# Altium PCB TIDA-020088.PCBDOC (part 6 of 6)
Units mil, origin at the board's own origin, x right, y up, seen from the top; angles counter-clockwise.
Board outline 7520.69 x 5119.11 mil, 6 copper layers (TOP, GND02, SIG03, SIG04, GND05, BOTTOM), stack 87.024 mil thick; 539 components, 269 nets, 1479 pads, 2085 vias.
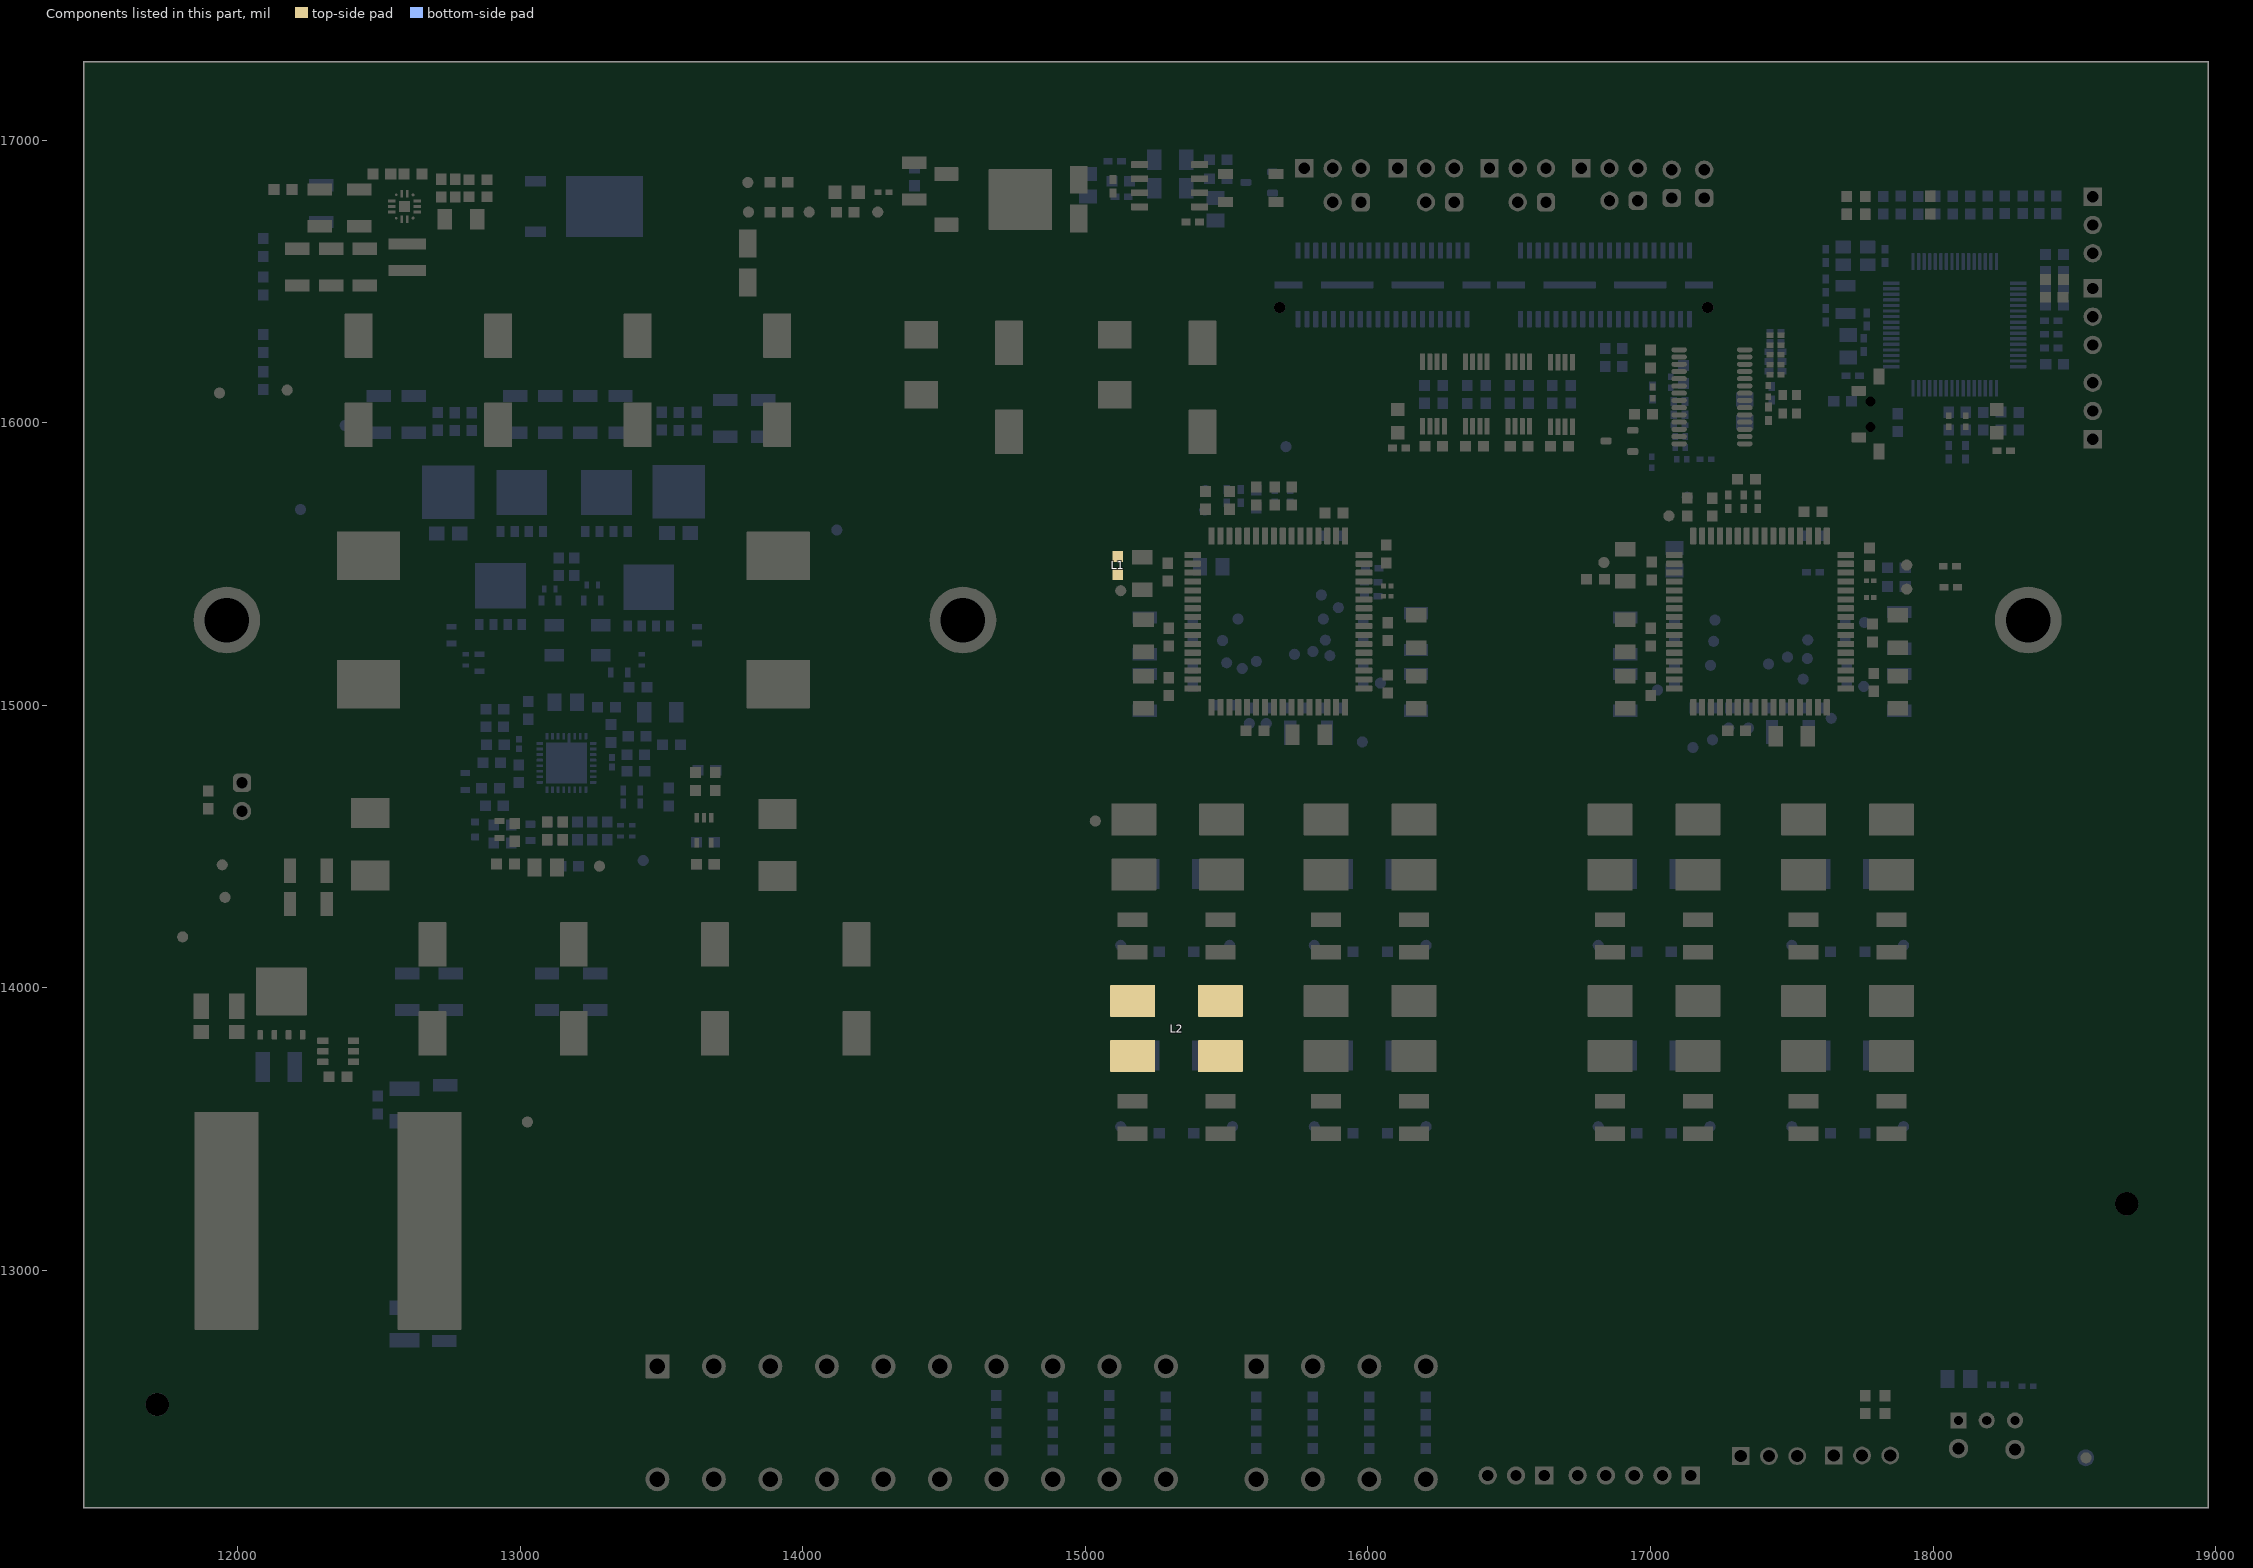
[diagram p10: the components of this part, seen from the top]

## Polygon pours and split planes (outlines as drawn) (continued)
PVDD_2 on TOP "PVDD_2_L01_P1359" (solid, pour order 1359): 19 vertices, not listed, extent 16790,14870 17165,15070
GND on TOP "GND_L01_P1358" (solid, pour order 1358): 17061.82,15230.84 17111.61,15230.84 17119.89,15222.56 17119.89,15152.56 17111.55,15144.22 17111.55,15143.22 17045.55,15143.22 17034.89,15132.56 17034.89,15088.87 17013.58,15067.56 16779.89,15067.56 16774.89,15072.56 16774.89,15217.56 16788.17,15230.84
PVDD_2 on TOP "PVDD_2_L01_P1357" (solid, pour order 1357): 17010,15360 17035,15385 17115,15385 17120,15380 17120,15310 17110,15300 17045,15300 17035,15290 17035,15246.47 17028.53,15240 16800,15240 16775,15265 16775,15340 16795,15360
NETC13_1 on TOP "NETC13_1_L01_P1356" (solid, pour order 1356): 15300,15475 15105,15475 15092.5,15462.5 15092.5,15407.5 15110,15390 15300,15390 15312.2,15402.2 15312.2,15462.8
NETC65_1 on TOP "NETC65_1_L01_P1355" (solid, pour order 1355): 17020,15470 16825,15470 16812.5,15457.5 16812.5,15402.5 16830,15385 17020,15385 17032.2,15397.2 17032.2,15457.8
BIAS on TOP "BIAS_L01_P1349" (solid, pour order 1349): 16785,15540 16665,15540 16652.5,15527.5 16652.5,15432.5 16670,15415 16780,15415 16795,15430 16795,15530
NETC37_2 on TOP "NETC37_2_L01_P1299" (solid, pour order 1299): 20 vertices, not listed, extent 15875,14520 16255,15025
GND on TOP "GND_L01_P1293" (solid, pour order 1293): 15780,15022.2 15781.34,15023.54 15831.46,15023.54 15835,15020 15835,14965 15835,14955 15855,14935 15865,14935 15885,14915 15885,14735 15875,14725 15790,14725 15780,14735
PVDD_1 on TOP "PVDD_1_L01_P1292" (solid, pour order 1292): 15660,15025 15705,15025 15710.55,15019.45 15710.55,14959.45 15720,14950 15765,14950 15775,14940 15775,14775 15755,14755 15630,14755 15610,14775 15610,14935 15625,14950 15655,14950 15655,15020
NETC29_2 on TOP "NETC29_2_L01_P1344" (solid, pour order 1344): 15391.07,14675.47 15629.53,14675.47 15645.49,14659.51 15645.49,14540.49 15630.47,14525.47 15394.91,14525.47 15372.47,14547.91 15372.47,14656.88
NETC38_1 on TOP "NETC38_1_L01_P1343" (solid, pour order 1343): 15686.07,14670.47 15924.53,14670.47 15940.49,14654.51 15940.49,14535.49 15925.47,14520.47 15689.91,14520.47 15667.47,14542.91 15667.47,14651.88
NETC90_1 on TOP "NETC90_1_L01_P1338" (solid, pour order 1338): 17375.47,14675.47 17614.53,14675.47 17635,14655 17635,14545 17615.47,14525.47 17369.9,14525.47 17360,14535.38 17360,14660
NETC97_2 on TOP "NETC97_2_L01_P1337" (solid, pour order 1337): 17766.07,14030.47 18004.53,14030.47 18020.49,14014.51 18020.49,13895.49 18005.47,13880.47 17769.9,13880.47 17747.47,13902.91 17747.47,14011.88
NETC74_1 on TOP "NETC74_1_L01_P1328" (solid, pour order 1328): 16686.07,14030.47 16924.53,14030.47 16940.49,14014.51 16940.49,13895.49 16925.47,13880.47 16689.9,13880.47 16667.47,13902.91 16667.47,14011.88
NETC45_2 on TOP "NETC45_2_L01_P1323" (solid, pour order 1323): 16086.07,14030.47 16324.53,14030.47 16340.49,14014.51 16340.49,13895.49 16325.47,13880.47 16089.91,13880.47 16067.47,13902.91 16067.47,14011.88
NETC19_2 on TOP "NETC19_2_L01_P1321" (solid, pour order 1321): 15393.08,14023.08 15671.92,14023.08 15689.48,14005.52 15689.48,13894.48 15668.08,13873.08 15396.92,13873.08 15374.48,13895.52 15374.48,14004.48
NETC22_1 on TOP "NETC22_1_L01_P1310" (solid, pour order 1310): 14971.16,14025 15250,14025 15267.56,14007.44 15267.56,13896.4 15246.16,13875 14975,13875 14952.56,13897.44 14952.56,14006.4
BIAS on TOP "BIAS_L01_P1309" (solid, pour order 1309): 14825,15565 15125,15565 15143.54,15546.46 15143.54,15513.54 15125,15495 15015,15495 14965,15445 14830,15445 14810,15465 14810,15550
PVDD_1 on TOP "PVDD_1_L01_P1305" (solid, pour order 1305): 18 vertices, not listed, extent 15954.22,15270 16225,15360
GND on TOP "GND_L01_P1303" (solid, pour order 1303): 19 vertices, not listed, extent 15950,15077.32 16225,15250.87
NETC45_2 on TOP "NETC45_2_L01_P1302" (solid, pour order 1302): 16017.95,15274.73 16012.95,15269.73 15947.95,15269.73 15927.95,15249.73 15872.95,15249.73 15862.95,15259.73 15862.95,15314.73 15872.95,15324.73 15927.95,15324.73 15937.95,15314.73 15937.95,15294.73 15942.95,15289.73 16012.95,15289.73 16017.95,15284.73
NETC46_1 on TOP "NETC46_1_L01_P1301" (solid, pour order 1301): 16018.18,15085.8 16013.18,15080.8 15948.18,15080.8 15928.18,15060.8 15873.18,15060.8 15863.18,15070.8 15863.18,15125.8 15873.18,15135.8 15928.18,15135.8 15938.18,15125.8 15938.18,15105.8 15943.18,15100.8 16013.18,15100.8 16018.18,15095.8
PVDD_1 on TOP "PVDD_1_L01_P1300" (solid, pour order 1300): 15956.26,15071.06 16107.04,15071.06 16120,15058.1 16120,15040 16135,15025 16210,15025 16225,15010 16225,14860 16200,14835 16105,14835 15980,14960 15911.28,14960 15905.81,14965.47 15905.81,15021.54 15955.33,15071.07
NETC38_1 on TOP "NETC38_1_L01_P1295" (solid, pour order 1295): 15765.02,15120.62 15775.02,15110.62 15775.02,15050.64 15742.2,15028.72 15742.2,14963.95 15740.28,14962.02 15720.39,14962.02 15717.86,14964.55 15717.86,15032.56 15698.77,15051.65 15698.77,15110.81 15708.59,15120.62
NETC29_2 on TOP "NETC29_2_L01_P1294" (solid, pour order 1294): 15670,15120 15680,15110 15680,15050.02 15647.19,15028.1 15647.19,14963.32 15645.26,14961.4 15625.37,14961.4 15622.84,14963.93 15622.84,15031.94 15603.76,15051.03 15603.76,15110.19 15613.57,15120
GND on TOP "GND_L01_P1291" (solid, pour order 1291): 15530,15027.2 15531.34,15028.54 15581.46,15028.54 15585,15025 15585,14955 15600,14940 15600,14820 15590,14810 15540,14810 15530,14820
PVDD_1 on TOP "PVDD_1_L01_P1288" (solid, pour order 1288): 19 vertices, not listed, extent 15085,14870 15460,15070
NETC19_2 on TOP "NETC19_2_L01_P1286" (solid, pour order 1286): 15345,15095 15350,15100 15415,15100 15435,15120 15490,15120 15500,15110 15500,15055 15490,15045 15435,15045 15425,15055 15425,15075 15420,15080 15350,15080 15345,15085
NETC22_1 on TOP "NETC22_1_L01_P1285" (solid, pour order 1285): 15350,15285 15355,15290 15415,15290 15425,15300 15425,15340 15435,15350 15495,15350 15505,15340 15505,15275 15495,15265 15355,15265 15350,15270
PVDD_1 on TOP "PVDD_1_L01_P1284" (solid, pour order 1284): 15110,15345 15290,15345 15330,15385 15410,15385 15415,15380 15415,15310 15405,15300 15340,15300 15330,15290 15330,15246.47 15323.53,15240 15100,15240 15090,15250 15090,15340 15095,15345
3.3V-SPDIF on TOP "3.3V-SPDIF_L01_P1276" (solid, pour order 1276): 16985,16045 16985,15975 16995,15965 17055,15965 17065,15975 17065,16047 17052,16060 17000,16060
VCC on TOP "VCC_L01_P1275" (solid, pour order 1275): 16830,16045 16830,16010 16840,16000 16960,16000 16970,16010 16970,16045 16960,16055 16840,16055
3V3 on TOP "3V3_L01_P1274" (solid, pour order 1274): 14280,16770 14170,16770 14157.5,16757.5 14157.5,16642.5 14170,16630 14275,16630 14290,16645 14290,16760
VCC on TOP "VCC_L01_P1273" (solid, pour order 1273): 14120,16900 13935,16900 13917.5,16882.5 13917.5,16647.5 13935,16630 14120,16630 14140,16650 14140,16880
VCC_BUCK on TOP "VCC_BUCK_L01_P1272" (solid, pour order 1272): 17 vertices, not listed, extent 12850,16455 13910,16900
VCC_LDO on TOP "VCC_LDO_L01_P1271" (solid, pour order 1271): 13150,16555 13185,16520 13665,16520 13715,16570 13865,16570 13910,16615 13910,16765 13890,16785 13695,16785 13665,16755 13665,16700 13620,16655 13185,16655 13150,16620
VCC_BUCK on TOP "VCC_BUCK_L01_P1266" (solid, pour order 1266): 12140,16510 12160,16530 12490,16530 12525,16565 12950,16565 12970,16545 12970,16475 12950,16455 12155,16455 12140,16470
NETL15_1 on TOP "NETL15_1_L01_P1265" (solid, pour order 1265): 17 vertices, not listed, extent 12525,16590 12675,16735
NetC120_1 on TOP "NETC120_1_L01_P1197" (solid, remove dead copper, pour order 1197): 12170,16840 12180,16850 12550,16850 12560,16840 12560,16765 12555,16760 12205,16760 12170,16795
BIAS on TOP "BIAS_L01_P1264" (solid, pour order 1264): 11815,16850 12145,16850 12155,16840 12155,16665 12120,16630 11810,16630 11785,16655 11785,16830 11805,16850
SW2 on TOP "SW2_L01_P1225" (solid, pour order 1225): 13725,15735 14220,15735 14235,15720 14235,15360 14210,15335 13645,15335 13290,15335 13260,15365 13260,15630 13270,15640 13675,15640 13700,15665 13700,15715
PVDD_2 on TOP "PVDD_2_L01_P1239" (solid, pour order 1239): 14995,16135 15030,16170 15165,16170 15220,16115 15565,16115 15635,16045 15635,15852.5 15607.5,15825 15017.5,15825 14995,15847.5
PVDD_1 on TOP "PVDD_1_L01_P1228" (solid, pour order 1228): 14332.5,16132.5 14367.5,16167.5 14502.5,16167.5 14557.5,16112.5 14902.5,16112.5 14972.5,16042.5 14972.5,15850 14945,15822.5 14355,15822.5 14332.5,15845
VOUT on TOP "VOUT_L01_P1227" (solid, pour order 1227): 14130,16175 14130,16500 14170,16540 14480,16540 14495,16525 14495,16390 14280,16175
VOUT on TOP "VOUT_L01_P1226" (solid, pour order 1226): 34 vertices, not listed, extent 11905,15650 15225,16540
L2 on TOP "L2_L01_P1221" (solid, pour order 1221): 14145,15280 13680,15280 13660,15260 13660,14900 13680,14880 14145,14880 14165,14900 14165,15260
L1 on TOP "L1_L01_P1219" (solid, pour order 1219): 12695,15280 12180,15280 12151.87,15251.87 12151.87,14593.13 12180,14565 12690,14565 12715,14590 12715,15260
BIAS on TOP "BIAS_L01_P1216" (solid, pour order 1216): 13385,14360 13770,14360 13800,14390 13800,14420 13829.14,14449.14 14001.72,14449.14 14365.86,14449.14 14395,14420 14395,14010 14370,13985 13385,13985
BAT_IN on TOP "BAT_IN_L01_P1201" (solid, pour order 1201): 13030,13575 13050,13555 13050,13450 13020,13420 12950,13420 12930,13400 12930,12810 12910,12790 12800,12790 12400,12790 12330,12860 12330,13520 12385,13575 12395,13575
BIAS on SIG03 "BIAS_L03_P1242" (solid, pour order 1242): 11870,14095 12430,14095 14375,14095 14395,14115 14395,14337.54 14372.54,14360 12630,14360 12560,14430 11880,14430 11710,14260 11710,14255
GND on SIG03 "GND_L03_P1534" (solid, remove dead copper, pour order 1534): 11450,17280 18967.57,17280 18967.57,12165.28 11450,12165.28
BIAS on SIG03 "BIAS_L03_P1354" (solid, pour order 1354): 15545.22,15540 16725,15540 16740.22,15524.78 16740.22,15475.22 16721.38,15456.38 14818.62,15456.38 14800,15475 14800,15515 14825,15540
AGND on SIG03 "AGND_L03_P1506" (solid, pour order 1506): 12725,14960 12725,14465 12785,14405 13470,14405 13565,14500 13565,15040 13555,15050 12815,15050
NETC74_1 on SIG03 "NETC74_1_L03_P1375" (solid, pour order 1375): 26 vertices, not listed, extent 16524.2,13890.22 17214.2,15360.22
NETC22_1 on SIG03 "NETC22_1_L03_P1319" (solid, pour order 1319): 27 vertices, not listed, extent 14815,13890 15505,15360
SPK_OUT4+ on SIG03 "SPK_OUT4+_L03_P1444" (solid, pour order 1444): 22 vertices, not listed, extent 15185,12185 16160,13480
SPK_OUT8+ on SIG03 "SPK_OUT8+_L03_P1464" (solid, pour order 1464): 17 vertices, not listed, extent 16110,12185 18040,13541
SPK_OUT7- on SIG03 "SPK_OUT7-_L03_P1463" (solid, pour order 1463): 21 vertices, not listed, extent 15962.63,12545 17572.97,14185.33
SPK_OUT6+ on SIG03 "SPK_OUT6+_L03_P1462" (solid, pour order 1462): 22 vertices, not listed, extent 15725,12210 17245,14130
SPK_OUT6- on SIG03 "SPK_OUT6-_L03_P1454" (solid, pour order 1454): 22 vertices, not listed, extent 15680,12560 16955,14190
SPK_OUT3- on SIG03 "SPK_OUT3-_L03_P1458" (solid, pour order 1458): 21 vertices, not listed, extent 15045,12545 15815,14180
SPK_OUT2+ on SIG03 "SPK_OUT2+_L03_P1455" (solid, pour order 1455): 15305,13990 15305,14070 15340,14105 15505,14105 15525,14085 15525,14040 15490,14005 15445,14005 15430,13990
SPK_OUT2+ on SIG03 "SPK_OUT2+_L03_P1436" (solid, pour order 1436): 15305,13990 15430,13990 15430,13160 15040,12770 15040,12320 14905,12185 14860,12185 14810,12235 14810,12320 14865,12375 14930,12440 14930,12890 15305,13265
SPK_OUT2- on SIG03 "SPK_OUT2-_L03_P1433" (solid, pour order 1433): 18 vertices, not listed, extent 14740,12570 15265,14185.22
SPK_OUT1- on SIG03 "SPK_OUT1-_L03_P1432" (solid, pour order 1432): 14964.89,13523.92 14964.97,13523.83 15086.17,13523.83 15105.48,13504.52 15105.48,13380.48 14735,13010 14735,12595 14710,12570 14570,12570 14540,12600 14540,13099.03
NETC97_2 on SIG03 "NETC97_2_L03_P1382" (solid, pour order 1382): 28 vertices, not listed, extent 17560,13885 18050.49,15324.73
NETC98_1 on SIG03 "NETC98_1_L03_P1380" (solid, pour order 1380): 17571.55,15140.31 17636.55,15140.31 17651.55,15125.31 17651.55,14060.31 17683.47,14028.39 17708.47,14028.39 17726.55,14010.31 17726.55,13900.31 17704.63,13878.39 17618.47,13878.39 17578.04,13918.82 17578.04,15017.37 17565.11,15030.31 17554.74,15040.68 17554.74,15123.49
NETC90_1 on SIG03 "NETC90_1_L03_P1379" (solid, pour order 1379): 18 vertices, not listed, extent 17362.47,14520 17540,15120.62
NETC81_2 on SIG03 "NETC81_2_L03_P1378" (solid, pour order 1378): 17299.73,15111.96 17309.54,15121.77 17373.98,15121.77 17383.34,15112.41 17383.34,14694.14 17340.97,14651.77 17340.97,14541.77 17326.45,14527.25 17261.45,14527.25 17260.97,14526.77 17245.97,14541.77 17245.97,14764.26 17299.73,14818.02
NETC71_2 on SIG03 "NETC71_2_L03_P1376" (solid, pour order 1376): 17130,15105 17150,15125 17205,15125 17225,15105 17225,14505 17375,14355 17375,13900 17365,13890 17270,13890 17250,13910 17250,14330 17130,14450
NETC45_2 on SIG03 "NETC45_2_L03_P1352" (solid, pour order 1352): 28 vertices, not listed, extent 15850,13880 16340.49,15319.73
NETC46_1 on SIG03 "NETC46_1_L03_P1350" (solid, pour order 1350): 15880,15135 15945,15135 15960,15120 15960,14055 15991.92,14023.08 16016.92,14023.08 16035,14005 16035,13895 16013.08,13873.08 15926.92,13873.08 15880,13920 15880,15018.56 15873.56,15025 15863.18,15035.37 15863.18,15118.19
NETC38_1 on SIG03 "NETC38_1_L03_P1348" (solid, pour order 1348): 18 vertices, not listed, extent 15667.47,14520 15845,15120.62
NETC29_2 on SIG03 "NETC29_2_L03_P1347" (solid, pour order 1347): 15595,15101.43 15613.57,15120 15678.01,15120 15687.37,15110.64 15687.37,14692.37 15645,14650 15645,14540 15630.47,14525.47 15565.47,14525.47 15565,14525 15550,14540 15550,14762.49 15595,14807.49
NETC19_2 on SIG03 "NETC19_2_L03_P1346" (solid, pour order 1346): 15415,15100 15435,15120 15490,15120 15510,15100 15510,14325 15545,14290 15640,14290 15660,14270 15660,13895 15650,13885 15555,13885 15535,13905 15535,14135 15415,14255
3.3V-SPDIF on SIG03 "3.3V-SPDIF_L03_P1278" (solid, pour order 1278): 17025,16335 17060,16370 17470,16370 17490,16350 17490,15965 17465,15940 17050,15940 17025,15965
BIAS on SIG03 "BIAS_L03_P1261" (solid, pour order 1261): 21 vertices, not listed, extent 11620,14171.36 12600,16805
VOUT on SIG03 "VOUT_L03_P1251" (solid, pour order 1251): 33 vertices, not listed, extent 12110,15650 15225,16540
PVDD_2 on SIG03 "PVDD_2_L03_P1255" (solid, pour order 1255): 14995,16135 15030,16170 15165,16170 15220,16115 15565,16115 15635,16045 15635,15852.5 15607.5,15825 15017.5,15825 14995,15847.5
PVDD_1 on SIG03 "PVDD_1_L03_P1256" (solid, pour order 1256): 14332.5,16132.5 14367.5,16167.5 14502.5,16167.5 14557.5,16112.5 14902.5,16112.5 14972.5,16042.5 14972.5,15850 14945,15822.5 14355,15822.5 14332.5,15845
VOUT on SIG03 "VOUT_L03_P1253" (solid, pour order 1253): 14130,16175 14130,16500 14170,16540 14480,16540 14495,16525 14495,16390 14280,16175
SW2 on SIG03 "SW2_L03_P1248" (solid, pour order 1248): 13725,15735 14220,15735 14235,15720 14235,15360 14210,15335 13645,15335 13290,15335 13260,15365 13260,15630 13270,15640 13675,15640 13700,15665 13700,15715
SW1 on SIG03 "SW1_L03_P1246" (solid, pour order 1246): 12190,15725 12600,15725 12625,15700 12625,15650 12635,15640 13091.54,15640 13100,15631.54 13100,15485 13100,15365 13085,15350 13070,15335 12210,15335 12175,15370 12175,15610 12175,15710
BAT_IN on SIG03 "BAT_IN_L03_P1199" (solid, pour order 1199): 14485,12475 12810,12475 12770,12515 12770,13540 12805,13575 14475,13575 14525,13525 14525,12515
BIAS on SIG04 "BIAS_L04_P1535" (solid, pour order 1535): 12035,16640 11955,16640 11940,16655 11940,16845 11989.32,16894.32 14204.32,16894.32 14265,16955 14345,16955 14365,16935 14365,16878.15 14296.85,16810 12105,16810 12050,16755 12050,16655
GND on SIG04 "GND_L04_P1538" (solid, remove dead copper, pour order 1538): 11448.8,17280.82 18966.37,17280.82 18966.37,12166.09 11448.8,12166.09
BIAS on SIG04 "BIAS_L04_P1532" (solid, pour order 1532): 14360,14360 14525,14360 14804.92,14639.92 14804.92,15544.92 14825,15565 14950,15565 14980,15535 14980,14475 14610,14105 14325,14105 14325,14325
3V3 on SIG04 "3V3_L04_P1505" (solid, pour order 1505): 26 vertices, not listed, extent 17440,16090 18640,16621.5
SPK_OUT8- on SIG04 "SPK_OUT8-_L04_P1461" (solid, pour order 1461): 17366.29,13510.32 17384.89,13528.92 17521.08,13528.92 17545,13505 17545,13295 16830,12580 16285,12580 16255,12550 16175,12550 16163.51,12561.49 16163.51,12708.51 16180,12725 16740,12725 17366.29,13351.29
SPK_OUT5+ on SIG04 "SPK_OUT5+_L04_P1448" (solid, pour order 1448): 27 vertices, not listed, extent 15480,12180 17350,13528.92
SPK_OUT1+ on SIG04 "SPK_OUT1+_L04_P1456" (solid, pour order 1456): 15500,13560 15645,13560 15657.3,13547.7 15657.3,13512.3 15600,13455 15495.09,13455 15475,13475.09 15475,13535
SPK_OUT4- on SIG04 "SPK_OUT4-_L04_P1439" (solid, pour order 1439): 18 vertices, not listed, extent 15205,12550 15805,13540
SPK_OUT3+ on SIG04 "SPK_OUT3+_L04_P1451" (solid, pour order 1451): 26 vertices, not listed, extent 15015,12180 16505,14195
SPK_OUT7+ on SIG04 "SPK_OUT7+_L04_P1446" (solid, pour order 1446): 23 vertices, not listed, extent 15940,12195 18045,14180
SPK_OUT5- on SIG04 "SPK_OUT5-_L04_P1443" (solid, pour order 1443): 19 vertices, not listed, extent 15535,12545 16840,13528.92
SPK_OUT1+ on SIG04 "SPK_OUT1+_L04_P1434" (solid, pour order 1434): 15477.5,13537.5 15545,13537.5 15545,13465 14840,12760 14840,12335 14685,12180 14630,12180 14575,12235 14575,12320 14590,12335 14630,12335 14730,12435 14730,12790
PVDD_1 on SIG04 "PVDD_1_L04_P1431" (solid, pour order 1431): 14375,15895 14685,15585 14945,15585 15090,15440 15090,15330 15695,15330 15705,15340 15690,15355 15645,15355 15315,15685 15205,15685 14935,15955 14395,15955 14375,15935
PVDD_2 on SIG04 "PVDD_2_L04_P1430" (solid, pour order 1430): 15035,16045 15015,16025 15015,15895 15215,15695 15330,15695 15625,15400 15860,15635 15860,15820 15635,16045
PVDD_2 on SIG04 "PVDD_2_L04_P1427" (solid, pour order 1427): 15330,15695 15625,15400 16205,15400 16270,15335 16270,14835 16330,14775 16940,14775 16940,15230 16940,15360 16480,15820 15860,15820 15635,16045 15330,16045
PVDD_2 on SIG04 "PVDD_2_L04_P1353" (solid, pour order 1353): 17857.67,14777.56 16817.67,14777.56 16777.67,14817.56 16777.67,15342.56 16797.67,15362.56 17877.67,15362.56 17912.67,15327.56 17912.67,14832.56
PVDD_1 on SIG04 "PVDD_1_L04_P1315" (solid, pour order 1315): 16120,14725 15180,14725 15090,14815 15090,15340 15110,15360 16190,15360 16225,15325 16225,14830
PVDD_1 on SIG04 "PVDD_1_L04_P1254" (solid, pour order 1254): 14392.5,16042.5 14952.5,16042.5 14972.5,16022.5 14972.5,15897.5 14950,15875 14395,15875 14375,15895 14375,16025
VOUT on SIG04 "VOUT_L04_P1250" (solid, pour order 1250): 20 vertices, not listed, extent 11905,15652.5 14180,16142.5
SW2 on SIG04 "SW2_L04_P1249" (solid, pour order 1249): 13725,15735 14220,15735 14235,15720 14235,15360 14210,15335 13645,15335 13290,15335 13260,15365 13260,15630 13270,15640 13675,15640 13700,15665 13700,15715
SW1 on SIG04 "SW1_L04_P1247" (solid, pour order 1247): 12190,15725 12600,15725 12625,15700 12625,15650 12635,15640 13091.54,15640 13100,15631.54 13100,15485 13100,15365 13085,15350 13070,15335 12210,15335 12175,15370 12175,15610 12175,15710
BIAS on SIG04 "BIAS_L04_P1243" (solid, pour order 1243): 12315,14105 14340,14105 14395,14160 14395,14330 14365,14360 14025,14360 13770,14360 12630,14360 12315,14360 12290,14335 12290,14130
BAT_IN on SIG04 "BAT_IN_L04_P1200" (solid, pour order 1200): 14515,12475 12810,12475 12770,12515 12770,13540 12805,13575 14505,13575 14560,13520 14560,12520
GND on GND02 "GND_L02_P1533" (solid, remove dead copper, pour order 1533): 11454.56,17277.48 18972.13,17277.48 18972.13,12162.76 11454.56,12162.76
no net on Bottom Solder "Bottom Solder-No Net" (solid): 132 vertices, not listed, extent 11474.56,12180 18954,17254.71

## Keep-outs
TOP:
  circle w1: c25911,29728 r42.87
  circle w1: c26096,29728 r42.87
  circle w1: c26281,29728 r42.87
  circle w1: c31621.51,22103.17 r42.87
BOTTOM:
  circle w1: c31621.51,22103.17 r42.87

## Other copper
TOP:
  region net GND: 11785.14,15300.05 ccw(c11962.31,15300.05) 11962.31,15122.88 ccw(c11962.31,15300.05) 12139.48,15300.05 ccw(c11962.31,15300.05) 11962.31,15477.22 ccw(c11962.31,15300.05)
  region net GND: 12913.62,13239.16 ccw(c13090.79,13239.16) 13090.79,13061.99 ccw(c13090.79,13239.16) 13267.96,13239.16 ccw(c13090.79,13239.16) 13090.79,13416.33 ccw(c13090.79,13239.16)
  region net GND: 14389.19,15301.87 ccw(c14566.36,15301.87) 14566.36,15124.7 ccw(c14566.36,15301.87) 14743.53,15301.87 ccw(c14566.36,15301.87) 14566.36,15479.04 ccw(c14566.36,15301.87)
  region net GND: 18154.9,15301.51 ccw(c18332.07,15301.51) 18332.07,15124.34 ccw(c18332.07,15301.51) 18509.24,15301.51 ccw(c18332.07,15301.51) 18332.07,15478.68 ccw(c18332.07,15301.51)
  region net GND: 15529.96,13241.68 ccw(c15707.13,13241.68) 15707.13,13064.51 ccw(c15707.13,13241.68) 15884.3,13241.68 ccw(c15707.13,13241.68) 15707.13,13418.85 ccw(c15707.13,13241.68)
  region net GND: 17694.33,13242 ccw(c17871.5,13242) 17871.5,13064.83 ccw(c17871.5,13242) 18048.67,13242 ccw(c17871.5,13242) 17871.5,13419.17 ccw(c17871.5,13242)
  region net GND: 12912.61,12523.24 ccw(c13089.78,12523.24) 13089.78,12346.07 ccw(c13089.78,12523.24) 13266.95,12523.24 ccw(c13089.78,12523.24) 13089.78,12700.41 ccw(c13089.78,12523.24)
BOTTOM:
  region net GND: 12913.62,13239.16 ccw(c13090.79,13239.16) 13090.79,13061.99 ccw(c13090.79,13239.16) 13267.96,13239.16 ccw(c13090.79,13239.16) 13090.79,13416.33 ccw(c13090.79,13239.16)
  region net GND: 11785.14,15300.05 ccw(c11962.31,15300.05) 11962.31,15122.88 ccw(c11962.31,15300.05) 12139.48,15300.05 ccw(c11962.31,15300.05) 11962.31,15477.22 ccw(c11962.31,15300.05)
  region net GND: 12912.61,12523.24 ccw(c13089.78,12523.24) 13089.78,12346.07 ccw(c13089.78,12523.24) 13266.95,12523.24 ccw(c13089.78,12523.24) 13089.78,12700.41 ccw(c13089.78,12523.24)
  region net GND: 14393.49,15301.88 ccw(c14570.66,15301.88) 14570.66,15124.71 ccw(c14570.66,15301.88) 14747.83,15301.88 ccw(c14570.66,15301.88) 14570.66,15479.05 ccw(c14570.66,15301.88)
  region net GND: 15529.96,13241.68 ccw(c15707.13,13241.68) 15707.13,13064.51 ccw(c15707.13,13241.68) 15884.3,13241.68 ccw(c15707.13,13241.68) 15707.13,13418.85 ccw(c15707.13,13241.68)
  region net GND: 18154.9,15301.51 ccw(c18332.07,15301.51) 18332.07,15124.34 ccw(c18332.07,15301.51) 18509.24,15301.51 ccw(c18332.07,15301.51) 18332.07,15478.68 ccw(c18332.07,15301.51)
  region net GND: 17694.33,13242 ccw(c17871.5,13242) 17871.5,13064.83 ccw(c17871.5,13242) 18048.67,13242 ccw(c17871.5,13242) 17871.5,13419.17 ccw(c17871.5,13242)
  region net GND: 15529.96,13241.68 ccw(c15707.13,13241.68) 15707.13,13064.51 ccw(c15707.13,13241.68) 15884.3,13241.68 ccw(c15707.13,13241.68) 15707.13,13418.85 ccw(c15707.13,13241.68)
Multi-Layer:
  pour cut-out: 18683.85,13173.77 cw(c18683.85,13235.4) 18622.21,13235.4 cw(c18683.85,13235.4) 18683.85,13297.04 cw(c18683.85,13235.4) 18745.48,13235.4 cw(c18683.85,13235.4)
  pour cut-out: 11715.15,12463.79 cw(c11715.15,12525.42) 11653.51,12525.42 cw(c11715.15,12525.42) 11715.15,12587.06 cw(c11715.15,12525.42) 11776.78,12525.42 cw(c11715.15,12525.42)

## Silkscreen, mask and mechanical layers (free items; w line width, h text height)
Top Overlay:
  drawing of 541 lines, arcs and shapes, not listed
  text "8" at 4396,27895 h35
  text "8" at 4396,27895 h35
  text "7" at 8521,27895 h35
  text "7" at 8521,27895 h35
  text "6" at 12646,27895 h35
  text "6" at 12646,27895 h35
  text "5" at 16771,27895 h35
  text "5" at 16771,27895 h35
  text "4" at 20896,27895 h35
  text "4" at 20896,27895 h35
  text "3" at 25021,27895 h35
  text "3" at 25021,27895 h35
  text "2" at 29146,27895 h35
  text "2" at 29146,27895 h35
  text "1" at 33271,27895 h35
  text "1" at 33271,27895 h35
  text "D" at 2181,25095 h35
  text "D" at 2181,25095 h35
  text "D" at 35445,25095 h125
  text "D" at 35445,25095 h125
  text "C" at 2181,19845 h35
  text "C" at 2181,19845 h35
  text "C" at 35445,19845 h125
  text "C" at 35445,19845 h125
  text "SDIN2" at 17430.81,16930.65 h30 r270
  text "SDIN1" at 17328.67,16926.92 h30 r270
  text "GPIO_MCU_15" at 18178,16788 h30
  text "GPIO1_1" at 17328,16772 h30 r270
  text "GPIO2_1" at 17435.65,16770.3 h30 r270
  text "FSYNC_SPDIF" at 16108,16702 h30 r270
  text "FSYNC" at 16208,16702 h30 r270
  text "SCLK" at 15865.33,16695.57 h30 r270
  text "SDIN1" at 16527.37,16695.73 h30 r270
  text "SDIN2" at 16850.14,16695.73 h30 r270
  text "GND" at 16306.2,16691.76 h30 r270
  text "GND" at 16624.92,16692.16 h30 r270
  text "GND" at 16947.69,16692.16 h30 r270
  text "GND" at 15960.33,16690.57 h30 r270
  text "GPIO_MCU_16" at 18178,16688 h30
  text "SDIN_SPDIF" at 16428,16687 h30 r270
  text "SCLK_SPDIF" at 15758,16682 h30 r270
  text "SDIN1" at 16748,16612 h30 r270
  text "GPIO_MCU_17" at 18176.78,16591.43 h30
  text "FSYNC" at 16208.5,16534.97 h30 r270
  text "SDIN1" at 16527.21,16535.37 h30 r270
  text "SDIN2" at 16849.99,16535.37 h30 r270
  text "ACLKX" at 15958,16532 h30 r270
  text "SCLK" at 15864.11,16524.02 h30 r270
  text "FSX" at 16303,16507 h30 r270
  text "AX0" at 16621.72,16507.4 h30 r270
  text "AX1" at 16944.49,16507.4 h30 r270
  text "SCL1" at 18385.67,16345.05 h30
  text "SDA1" at 18384.93,16287.72 h30
  text "3V3" at 18423,16123 h30
  text "BSL" at 18423,16013 h30
  text "GND" at 18413,15923 h30
  text "Layer" at 19495.64,15820 h60
  text "Name" at 19905.56,15820 h60
  text "Material" at 20835.3,15820 h60
  text "Thickness" at 21395.16,15820 h60
  text "Constant" at 22045,15820 h60
  text "Board Layer Stack" at 22614.86,15820 h60
  text "Top Overlay" at 19905.56,15700 h60
  text "Top Solder" at 19905.56,15580 h60
  text "SM-002" at 20835.3,15580 h60
  text "1.00mil" at 21395.16,15580 h60
  text "4" at 22045,15580 h60
  text "1" at 19495.64,15460 h60
  text "TOP" at 19905.56,15460 h60
  text "2.76mil" at 21395.16,15460 h60
  text "Dielectric1" at 19905.56,15340 h60
  text "FR-4" at 20835.3,15340 h60
  text "8.00mil" at 21395.16,15340 h60
  text "4.5" at 22045,15340 h60
  text "2" at 19495.64,15220 h60
  text "GND02" at 19905.56,15220 h60
  text "1.38mil" at 21395.16,15220 h60
  text "Dielectric2" at 19905.56,15100 h60
  text "FR-4" at 20835.3,15100 h60
  text "24.00mil" at 21395.16,15100 h60
  text "1" at 22045,15100 h60
  text "3" at 19495.64,14980 h60
  text "SIG03" at 19905.56,14980 h60
  text "1.38mil" at 21395.16,14980 h60
  text "Dielectric3" at 19905.56,14860 h60
  text "FR-4" at 20835.3,14860 h60
  text "12.00mil" at 21395.16,14860 h60
  text "1" at 22045,14860 h60
  text "4" at 19495.64,14740 h60
  text "SIG04" at 19905.56,14740 h60
  text "1.38mil" at 21395.16,14740 h60
  text "Dielectric4" at 19905.56,14620 h60
  text "FR-4" at 20835.3,14620 h60
  text "24.00mil" at 21395.16,14620 h60
  text "1" at 22045,14620 h60
  text "B" at 2181,14595 h35
  text "B" at 2181,14595 h35
  text "B" at 35445,14595 h125
  text "B" at 35445,14595 h125
  text "5" at 19495.64,14500 h60
  text "GND05" at 19905.56,14500 h60
  text "1.38mil" at 21395.16,14500 h60
  text "Dielectric5" at 19905.56,14380 h60
  text "FR-4" at 20835.3,14380 h60
  text "8.00mil" at 21395.16,14380 h60
  text "1" at 22045,14380 h60
  text "6" at 19495.64,14260 h60
  text "BOTTOM" at 19905.56,14260 h60
  text "2.76mil" at 21395.16,14260 h60
  text "Bottom Solder" at 19905.56,14140 h60
  text "SM-002" at 20835.3,14140 h60
  text "1.00mil" at 21395.16,14140 h60
  text "4" at 22045,14140 h60
  text "Bottom Overlay" at 19905.56,14020 h60
  text "1kW Automotive Class-H Audio Amplifier System Reference" at 15525,12955 h120
  text "TIDA-020088" at 18090,12865 h90
  text "GND" at 17531.09,12412.59 h30 r90
  text "CANL" at 17436.34,12409.59 h30 r90
  text "CANH" at 17332,12408 h30 r90
  text "GND" at 17608,12393 h30
  text "SCL" at 17713,12393 h30
  text "SDA" at 17813,12393 h30
  text "SWCLK" at 17152,12358 h30 r90
  text "UART_RX" at 16437,12353 h30 r90
  text "UART_TX" at 16534.91,12352.97 h30 r90
  text "GND" at 16647,12353 h30 r90
  text "3V3" at 16757,12353 h30 r90
  text "GND" at 16857,12353 h30 r90
  text "R\S\T\" at 16957,12353 h30 r90
  text "SWDIO" at 17057,12353 h30 r90
  text "A" at 35445,9345 h125
  text "A" at 35445,9345 h125
  text "8" at 4396,6540 h35
  text "8" at 4396,6540 h35
  text "7" at 8521,6540 h35
  text "7" at 8521,6540 h35
  text "6" at 12646,6540 h35
  text "6" at 12646,6540 h35
  text "5" at 16771,6540 h35
  text "5" at 16771,6540 h35
  text "4" at 20896,6540 h35
  text "4" at 20896,6540 h35
  text "3" at 25021,6540 h35
  text "3" at 25021,6540 h35
  text "2" at 29146,6540 h35
  text "2" at 29146,6540 h35
  text "1" at 33271,6540 h35
  text "1" at 33271,6540 h35
Bottom Overlay:
  circle w10: c18336.64,15301.37 r177.17
  circle w10: c14566.37,15301.37 r177.17
  circle w10: c11961.37,15301.37 r177.17
  circle w10: c13090.81,13239.66 r177.17
  circle w10: c13088.42,12522.76 r177.17
  circle w10: c15706.53,13241.89 r177.17
  circle w10: c17871.89,13242.05 r177.17
  lines w5: 1700,6265 35700,6265 ; 1700,6265 1700,28265 ; 1700,6265 35700,6265 ; 1700,6265 1700,28265 ; 1700,28265 35700,28265 ; 1700,28265 35700,28265 ; 35700,6265 35700,28265 ; 35700,6265 35700,28265
  lines w20: 2000,17165 2200,17265 ; 2000,17165 2000,17365 ; 2000,17165 2200,17265 ; 2000,17165 2000,17365 ; 2000,17365 2200,17265 ; 2000,17365 2200,17265 ; 2200,6765 35200,6765 ; 2200,6765 2200,27765 ; 2200,6765 35200,6765 ; 2200,6765 2200,27765 ; 2200,17265 1800,17265 2200,17265 ; 2200,27765 35200,27765 ; 2200,27765 35200,27765 ; 18600,6565 18800,6565 ; 18600,6565 18700,6765 ; 18600,6565 18800,6565 ; 18600,6565 18700,6765 ; 18600,27965 18800,27965 ; 18600,27965 18700,27765 ; 18600,27965 18800,27965 ; 18600,27965 18700,27765 ; 18700,6765 18800,6565 ; 18700,6765 18700,6365 18700,6765 ; 18700,6765 18800,6565 ; 18700,27765 18800,27965 ; 18700,27765 18700,28165 18700,27765 ; 18700,27765 18800,27965 ; 35200,6765 35200,27765 ; 35200,6765 35200,27765 ; 35200,17265 35600,17265 35200,17265 ; 35200,17265 35400,17365 ; 35200,17265 35400,17165 ; 35200,17265 35400,17365 ; 35200,17265 35400,17165 ; 35400,17165 35400,17365 ; 35400,17165 35400,17365 ; 1800,22515 2200,22515 1800,22515 ; 6325,6365 6325,6765 6325,6365 ; 6325,27765 6325,28165 6325,27765 ; 10450,6365 10450,6765 10450,6365 ; 10450,27765 10450,28165 10450,27765 ; 14575,6365 14575,6765 14575,6365 ; 14575,27765 14575,28165 14575,27765 ; 22825,6365 22825,6765 22825,6365 ; 22825,27765 22825,28165 22825,27765 ; 26950,6365 26950,6765 26950,6365 ; 26950,27765 26950,28165 26950,27765 ; 31075,6365 31075,6765 31075,6365 ; 31075,27765 31075,28165 31075,27765 ; 35200,12015 35600,12015 35200,12015 ; 35200,22515 35600,22515 35200,22515
  text "8" at 4396,27895 h35
  text "8" at 4396,27895 h35
  text "7" at 8521,27895 h35
  text "7" at 8521,27895 h35
  text "6" at 12646,27895 h35
  text "6" at 12646,27895 h35
  text "5" at 16771,27895 h35
  text "5" at 16771,27895 h35
  text "4" at 20896,27895 h35
  text "4" at 20896,27895 h35
  text "3" at 25021,27895 h35
  text "3" at 25021,27895 h35
  text "2" at 29146,27895 h35
  text "2" at 29146,27895 h35
  text "1" at 33271,27895 h35
  text "1" at 33271,27895 h35
  text "D" at 2181,25095 h35
  text "D" at 2181,25095 h35
  text "D" at 35445,25095 h125
  text "D" at 35445,25095 h125
  text "C" at 2181,19845 h35
  text "C" at 2181,19845 h35
  text "C" at 35445,19845 h125
  text "C" at 35445,19845 h125
  text "B" at 2181,14595 h35
  text "B" at 2181,14595 h35
  text "B" at 35445,14595 h125
  text "B" at 35445,14595 h125
  text "A" at 35445,9345 h125
  text "A" at 35445,9345 h125
  text "8" at 4396,6540 h35
  text "8" at 4396,6540 h35
  text "7" at 8521,6540 h35
  text "7" at 8521,6540 h35
  text "6" at 12646,6540 h35
  text "6" at 12646,6540 h35
  text "5" at 16771,6540 h35
  text "5" at 16771,6540 h35
  text "4" at 20896,6540 h35
  text "4" at 20896,6540 h35
  text "3" at 25021,6540 h35
  text "3" at 25021,6540 h35
  text "2" at 29146,6540 h35
  text "2" at 29146,6540 h35
  text "1" at 33271,6540 h35
  text "1" at 33271,6540 h35
Top Solder:
  pour cut-out: 12952.5,12666.67 11750.15,12666.67 11750.15,16979.12 18678.41,16979.12 18678.41,13376.69 12952.5,13376.69 12952.5,12666.67
Bottom Solder:
  pour cut-out: 11715.15,12463.79 cw(c11715.15,12525.42) 11653.51,12525.42 cw(c11715.15,12525.42) 11715.15,12587.06 cw(c11715.15,12525.42) 11776.78,12525.42 cw(c11715.15,12525.42)
  pour cut-out: 15529.96,13241.68 ccw(c15707.13,13241.68) 15707.13,13064.51 ccw(c15707.13,13241.68) 15884.3,13241.68 ccw(c15707.13,13241.68) 15707.13,13418.85 ccw(c15707.13,13241.68)
OUTLINE:
  lines w6.5: 11454.56,12159.37 11454.56,17277.48 ; 11454.56,12159.37 18974.25,12159.37 ; 11454.56,12159.37 18974.25,12159.37 ; 11454.56,12159.37 11454.56,17277.48 ; 11454.56,17277.48 18974.25,17277.48 ; 11454.56,17277.48 18974.25,17277.48 ; 18974.25,12159.37 18974.25,17277.48 ; 18974.25,12159.37 18974.25,17277.48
